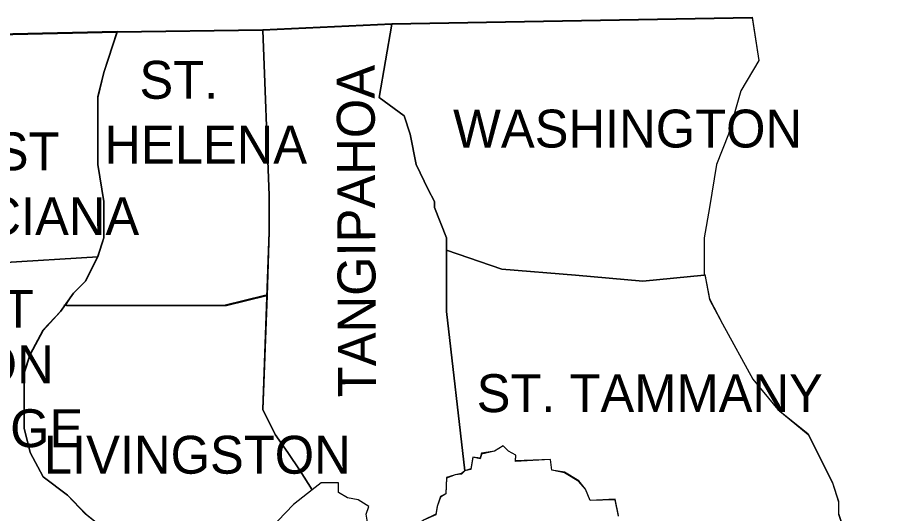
# Model space of a CAD drawing. Extents: x 0.19 to 2.82, y 0.04 to 1.79.
# Drawn here: x 2.4368 to 2.5436, y 1.5215 to 1.5827 of the extents above; entities that cross this region are included whole.
import ezdxf

# ---------------------------------------------------------------- set-up
doc = ezdxf.new("R2010")
doc.units = 0
for name, color, linetype in [('Dist61', 7, 'Continuous'), ('Dist62', 7, 'Continuous'), ('Standard Info', 7, 'Continuous')]:
    doc.layers.add(name, color=color, linetype=linetype)

msp = doc.modelspace()

# ---------------------------------------------------------------- linework, layer by layer
at = {"layer": 'Dist61'}
for points in [[(2.44915, 1.581), (2.42332, 1.58042)], [(2.44674, 1.55325), (2.44749, 1.5555), (2.44749, 1.56008), (2.44674, 1.56458), (2.44674, 1.56983), (2.44674, 1.57292), (2.44749, 1.57592), (2.44915, 1.581)], [(2.44524, 1.5215), (2.44299, 1.52375), (2.43999, 1.526), (2.4384, 1.529), (2.43765, 1.53208), (2.43765, 1.53508), (2.43765, 1.53892), (2.4384, 1.54117), (2.43999, 1.54417), (2.44215, 1.54642), (2.44374, 1.54867), (2.44524, 1.55017), (2.44674, 1.55325)], [(2.4634, 1.50633), (2.4634, 1.51167), (2.46265, 1.51242), (2.46115, 1.51092), (2.45957, 1.50783), (2.45882, 1.50867), (2.45732, 1.51017), (2.45582, 1.51242), (2.45207, 1.51617), (2.44899, 1.51842), (2.44515, 1.5215)]]:
    msp.add_lwpolyline(points, dxfattribs=at)
at = {"layer": 'Dist62'}
for p, q in [((2.48307, 1.582), (2.52757, 1.58275)), ((2.44915, 1.581), (2.46715, 1.58125)), ((2.46715, 1.58125), (2.48307, 1.582))]:
    msp.add_line(p, q, dxfattribs=at)
for points in [[(2.52757, 1.58275), (2.5284, 1.57742), (2.52615, 1.57367), (2.52465, 1.56833), (2.52315, 1.56458), (2.52232, 1.55925), (2.52165, 1.5555), (2.52165, 1.551)], [(2.44674, 1.55325), (2.44749, 1.5555), (2.44749, 1.56008), (2.44674, 1.56458), (2.44674, 1.56983), (2.44674, 1.57292), (2.44749, 1.57592), (2.44915, 1.581)], [(2.44524, 1.5215), (2.44299, 1.52375), (2.43999, 1.526), (2.4384, 1.529), (2.43765, 1.53208), (2.43765, 1.53508), (2.43765, 1.53892), (2.4384, 1.54117), (2.43999, 1.54417), (2.44215, 1.54642), (2.44374, 1.54867), (2.44524, 1.55017), (2.44674, 1.55325)], [(2.52174, 1.551), (2.52232, 1.548), (2.5239, 1.54492), (2.52765, 1.53808), (2.53074, 1.53433), (2.53449, 1.53133), (2.53749, 1.52525), (2.53824, 1.523), (2.53824, 1.5215), (2.53974, 1.51692), (2.54049, 1.51467), (2.54199, 1.51317), (2.54357, 1.51167), (2.53949, 1.50708)], [(2.51107, 1.52125), (2.51065, 1.52325), (2.50757, 1.52308), (2.50699, 1.5245), (2.50615, 1.5255), (2.5044, 1.52658), (2.50282, 1.52683), (2.50265, 1.52817), (2.49832, 1.528), (2.4984, 1.52867), (2.49749, 1.52917), (2.49682, 1.52983), (2.49574, 1.52917), (2.49415, 1.52892), (2.49399, 1.52833), (2.49307, 1.52842), (2.49282, 1.527), (2.49207, 1.52675)], [(2.49207, 1.52675), (2.49165, 1.52642), (2.4909, 1.52625), (2.48982, 1.52592), (2.48974, 1.52392), (2.48907, 1.52358), (2.48865, 1.52233), (2.48849, 1.52142), (2.48699, 1.52067), (2.48607, 1.51992), (2.48607, 1.51842)], [(2.4634, 1.50633), (2.4634, 1.51167), (2.46265, 1.51242), (2.46115, 1.51092), (2.45957, 1.50783), (2.45882, 1.50867), (2.45732, 1.51017), (2.45582, 1.51242), (2.45207, 1.51617), (2.44899, 1.51842), (2.44515, 1.5215)]]:
    msp.add_lwpolyline(points, dxfattribs=at)
at = {"layer": 'Standard Info'}
for p, q in [((2.48307, 1.58192), (2.52757, 1.58267)), ((2.46715, 1.58117), (2.48307, 1.58192)), ((2.44915, 1.58092), (2.46715, 1.58117)), ((2.52165, 1.55092), (2.52174, 1.551)), ((2.46765, 1.54842), (2.46732, 1.54842))]:
    msp.add_line(p, q, dxfattribs=at)
for points in [[(2.52757, 1.58267), (2.5284, 1.57742), (2.52615, 1.57367), (2.52465, 1.56833), (2.52315, 1.56458), (2.52232, 1.55925), (2.52165, 1.5555), (2.52165, 1.55092)], [(2.48307, 1.58192), (2.48149, 1.57283), (2.48457, 1.57058), (2.48532, 1.56833), (2.48607, 1.56458), (2.48757, 1.5615), (2.48832, 1.56), (2.48832, 1.55925), (2.48982, 1.5555), (2.48982, 1.54642), (2.49207, 1.52675)], [(2.48982, 1.554), (2.48982, 1.5555), (2.48832, 1.55925), (2.48832, 1.56), (2.48757, 1.5615), (2.48607, 1.56458), (2.48532, 1.56833), (2.48457, 1.57058), (2.48149, 1.57283), (2.48307, 1.58192)], [(2.42332, 1.58033), (2.44915, 1.58092)], [(2.44915, 1.58092), (2.44749, 1.57592), (2.44674, 1.57283), (2.44674, 1.56983), (2.44674, 1.56458), (2.44749, 1.56), (2.44749, 1.5555), (2.44674, 1.55317)], [(2.44674, 1.55317), (2.44749, 1.5555), (2.44749, 1.56), (2.44674, 1.56458), (2.44674, 1.56983), (2.44674, 1.57283), (2.44749, 1.57592), (2.44915, 1.58092)], [(2.46715, 1.58117), (2.4679, 1.56075), (2.4679, 1.55625), (2.46765, 1.54842)], [(2.47324, 1.52442), (2.47324, 1.52442), (2.47174, 1.52675), (2.47024, 1.529), (2.46865, 1.53125), (2.46715, 1.53433), (2.4679, 1.55625), (2.4679, 1.56075), (2.46715, 1.58117)], [(2.52165, 1.55092), (2.51407, 1.55017), (2.50574, 1.55092), (2.49665, 1.55167), (2.48982, 1.554)], [(2.49207, 1.52675), (2.48982, 1.54642), (2.48982, 1.554)], [(2.48982, 1.554), (2.49665, 1.55167), (2.50574, 1.55092), (2.51407, 1.55017), (2.52165, 1.55092)], [(2.4119, 1.54717), (2.41499, 1.54717), (2.41424, 1.55017), (2.41574, 1.55017), (2.41574, 1.55167), (2.42332, 1.55167), (2.43465, 1.55242), (2.44674, 1.55317)], [(2.44674, 1.55317), (2.43465, 1.55242), (2.42332, 1.55167), (2.41574, 1.55167), (2.41574, 1.55017), (2.41424, 1.55017), (2.41499, 1.54717), (2.41274, 1.54717)], [(2.44674, 1.55317), (2.44524, 1.55017), (2.44374, 1.54867), (2.44215, 1.54642), (2.43999, 1.54408), (2.4384, 1.54108), (2.43765, 1.53883), (2.43765, 1.535), (2.43765, 1.532), (2.4384, 1.529), (2.43999, 1.526), (2.44299, 1.52375), (2.44524, 1.52142)], [(2.44274, 1.54717), (2.44374, 1.54867), (2.44524, 1.55017), (2.44674, 1.55317)], [(2.52174, 1.551), (2.52232, 1.54792), (2.5239, 1.54492), (2.52765, 1.53808), (2.53074, 1.53433), (2.53449, 1.53125), (2.53749, 1.52525), (2.53824, 1.52292), (2.53824, 1.52142), (2.53974, 1.51692), (2.54049, 1.51467), (2.54199, 1.51317), (2.54357, 1.51158), (2.53949, 1.50708)], [(2.46732, 1.54842), (2.46232, 1.54717), (2.44257, 1.54717)], [(2.4429, 1.54717), (2.46265, 1.54717), (2.46765, 1.54842)], [(2.4429, 1.54717), (2.46265, 1.54717), (2.46765, 1.54842)], [(2.46765, 1.54842), (2.46715, 1.53433), (2.46865, 1.53125), (2.47024, 1.529), (2.47174, 1.52675), (2.47324, 1.52442)], [(2.46265, 1.51233), (2.46115, 1.51083), (2.45957, 1.50783), (2.45882, 1.50858), (2.45732, 1.51008), (2.45582, 1.51233), (2.45207, 1.51617), (2.44899, 1.51842), (2.44524, 1.52142), (2.44299, 1.52375), (2.43999, 1.526), (2.4384, 1.529), (2.43765, 1.532), (2.43765, 1.535), (2.43765, 1.53883), (2.4384, 1.54108), (2.43999, 1.54408), (2.44215, 1.54642), (2.44274, 1.54725)], [(2.51107, 1.52117), (2.51065, 1.52317), (2.50757, 1.52308), (2.50699, 1.5245), (2.50615, 1.52542), (2.5044, 1.5265), (2.50282, 1.52683), (2.50265, 1.52817), (2.49832, 1.52792), (2.4984, 1.52867), (2.49749, 1.52917), (2.49682, 1.52983), (2.49574, 1.52917), (2.49415, 1.52883), (2.49399, 1.52825), (2.49307, 1.52842), (2.49282, 1.52692), (2.49207, 1.52675)], [(2.49207, 1.52675), (2.49165, 1.52633), (2.4909, 1.52625), (2.48982, 1.52583), (2.48974, 1.52392), (2.48907, 1.5235), (2.48865, 1.52233), (2.48849, 1.52133), (2.48699, 1.52067), (2.48607, 1.51992), (2.48607, 1.51842)], [(2.47924, 1.51767), (2.47949, 1.51817), (2.48057, 1.51842), (2.4809, 1.52017), (2.48007, 1.52042), (2.4799, 1.52142), (2.48024, 1.52233), (2.4789, 1.52317), (2.47757, 1.52342), (2.47649, 1.52408), (2.47649, 1.52525), (2.47432, 1.52525), (2.47324, 1.52442)], [(2.47324, 1.52442), (2.4709, 1.52258), (2.46899, 1.52058), (2.46782, 1.51858), (2.4679, 1.5155), (2.46865, 1.5155), (2.46865, 1.51392), (2.4664, 1.51383), (2.46265, 1.51233)]]:
    msp.add_lwpolyline(points, dxfattribs=at)

# ---------------------------------------------------------------- texts
for s, p in [('ST.', (2.45189, 1.57269)), ('WASHINGTON', (2.49063, 1.56667)), ('EAST', (2.42568, 1.56386)), ('HELENA', (2.44756, 1.56469)), ('FELICIANA', (2.41953, 1.55586)), ('EAST', (2.42249, 1.54442)), ('BATON', (2.41974, 1.53756)), ('ST. TAMMANY', (2.49354, 1.534)), ('ROUGE', (2.42202, 1.52967)), ('LIVINGSTON', (2.44009, 1.5264))]:
    msp.add_text(s, height=0.004679, dxfattribs=at).set_placement(p)
msp.add_text('TANGIPAHOA', height=0.004679, rotation=90.2537, dxfattribs=at).set_placement((2.48111, 1.53585))

doc.saveas('drawing.dxf')
